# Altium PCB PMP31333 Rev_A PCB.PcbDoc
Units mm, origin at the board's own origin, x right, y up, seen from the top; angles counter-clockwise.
Board outline 35.48 x 25.63 mm, 2 copper layers (Top Layer, Bottom Layer), stack 1.575 mm thick; 18 components, 11 nets, 50 pads, 12 vias.
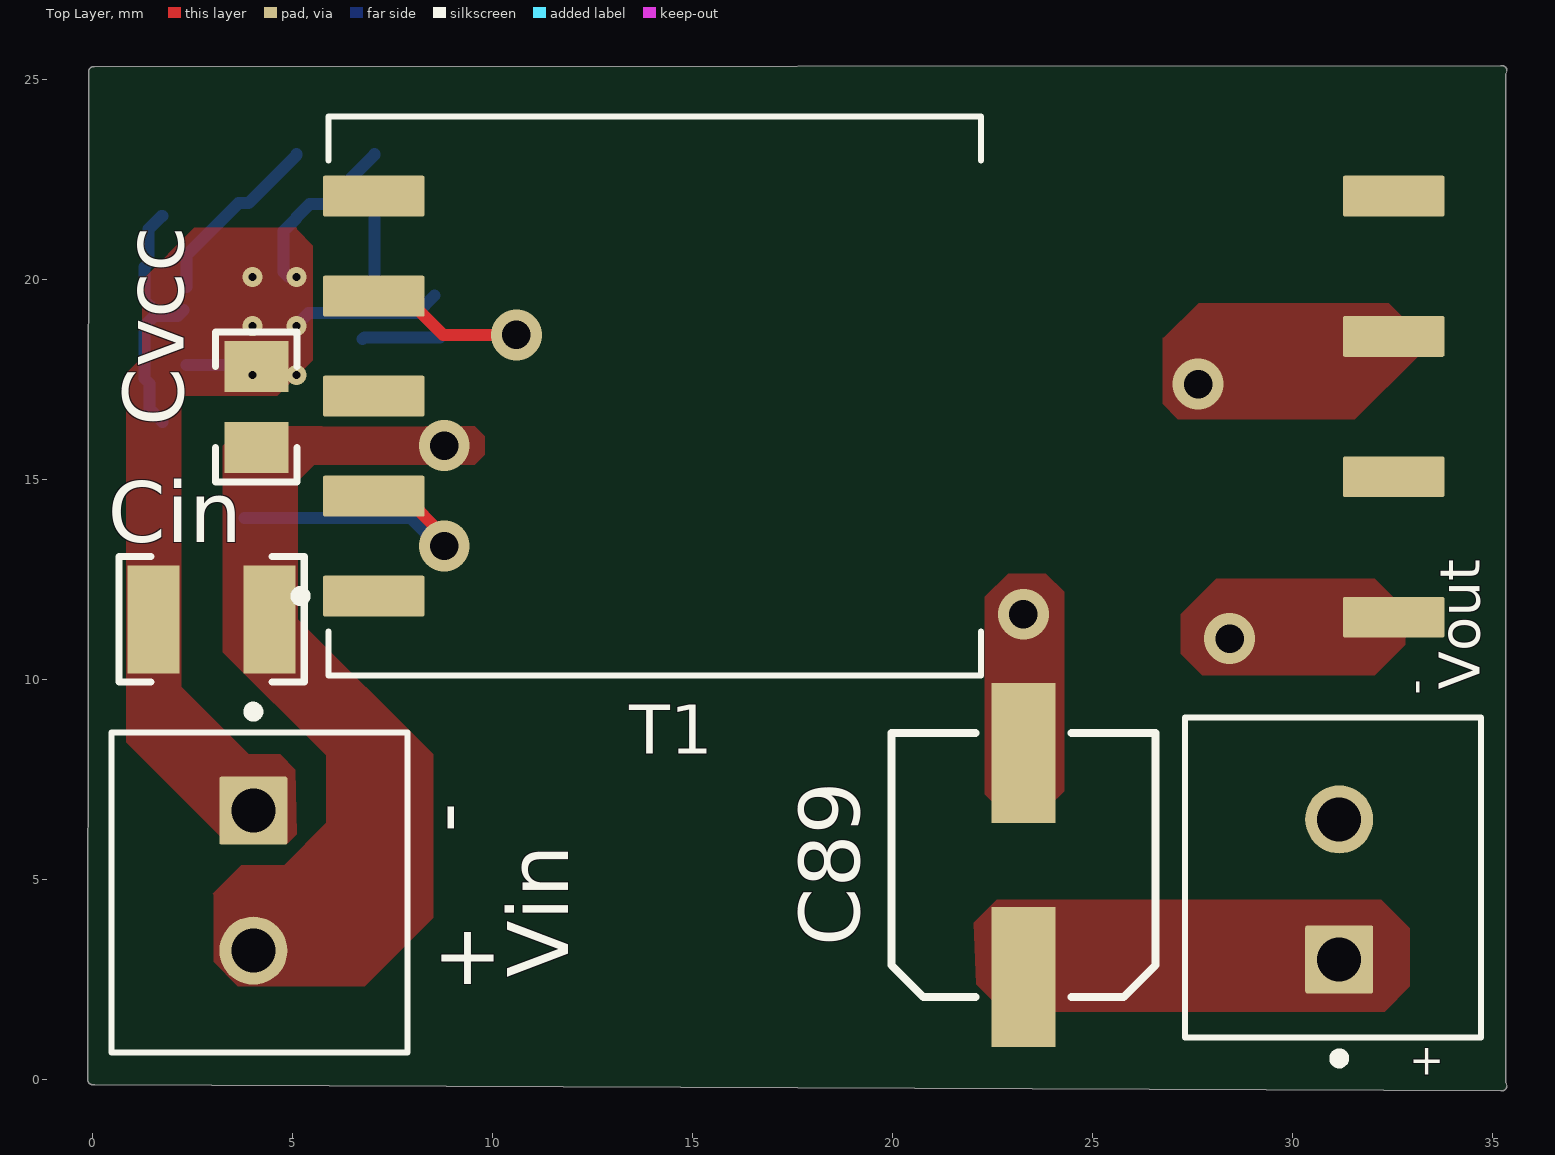
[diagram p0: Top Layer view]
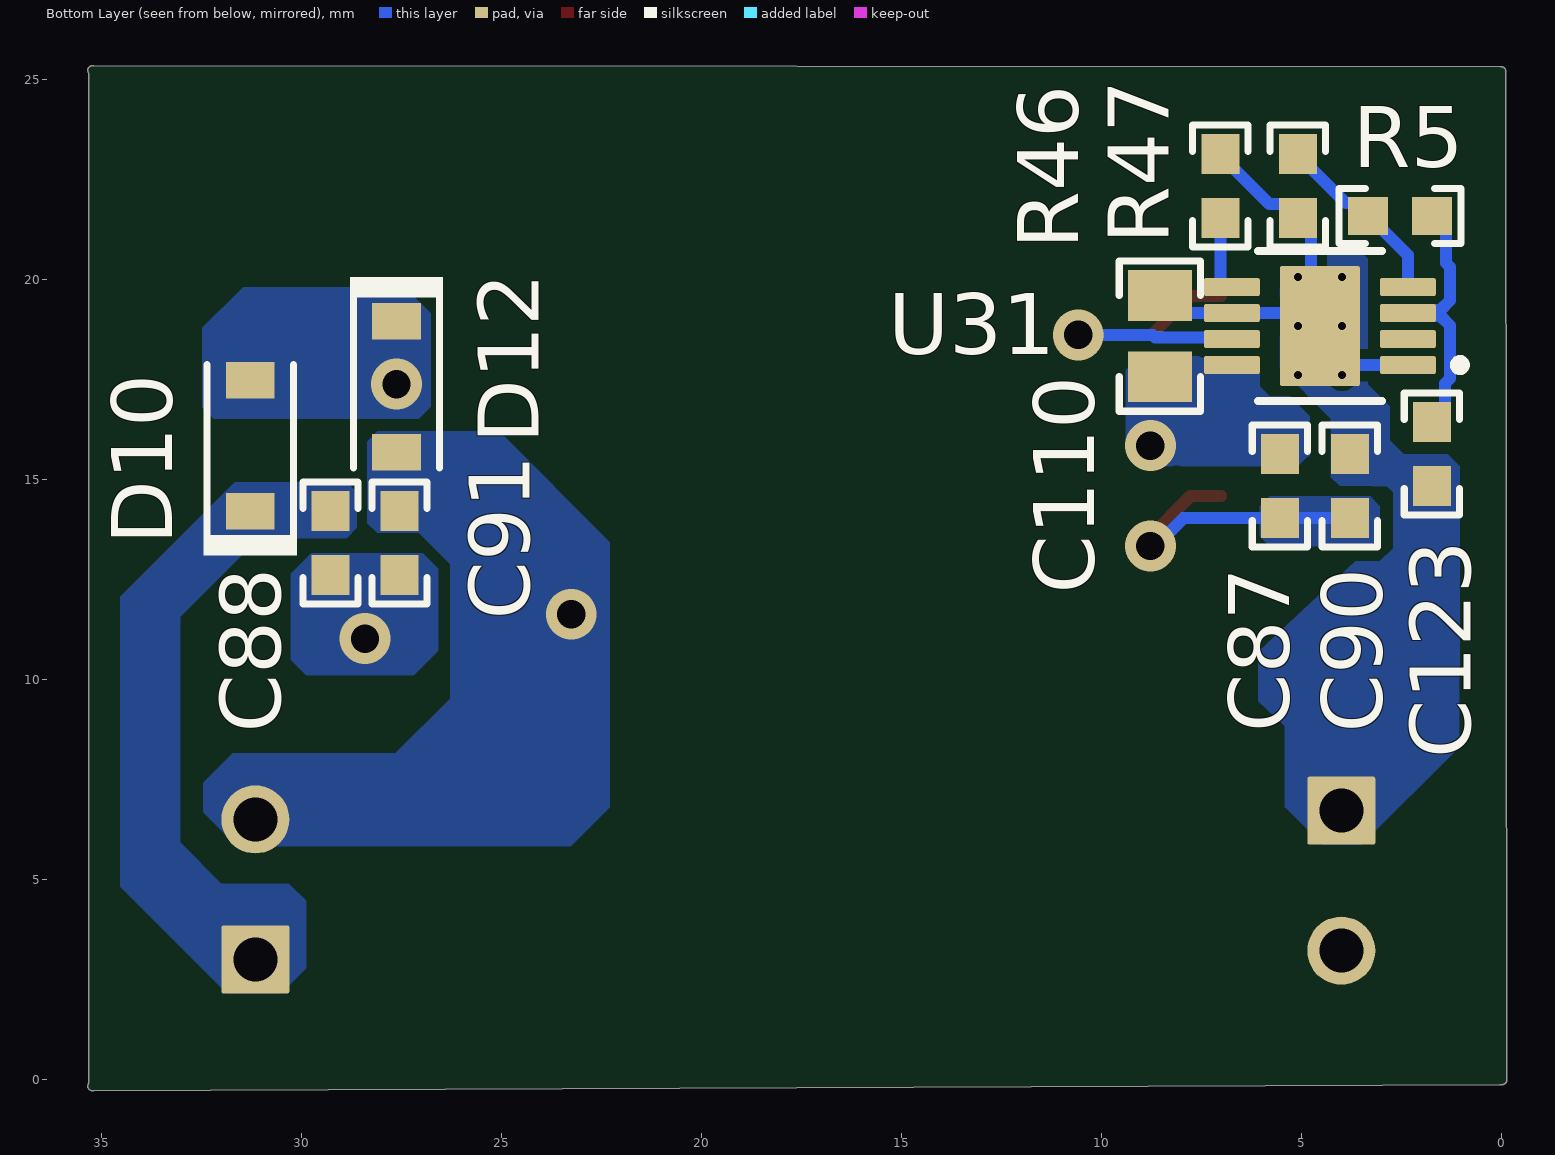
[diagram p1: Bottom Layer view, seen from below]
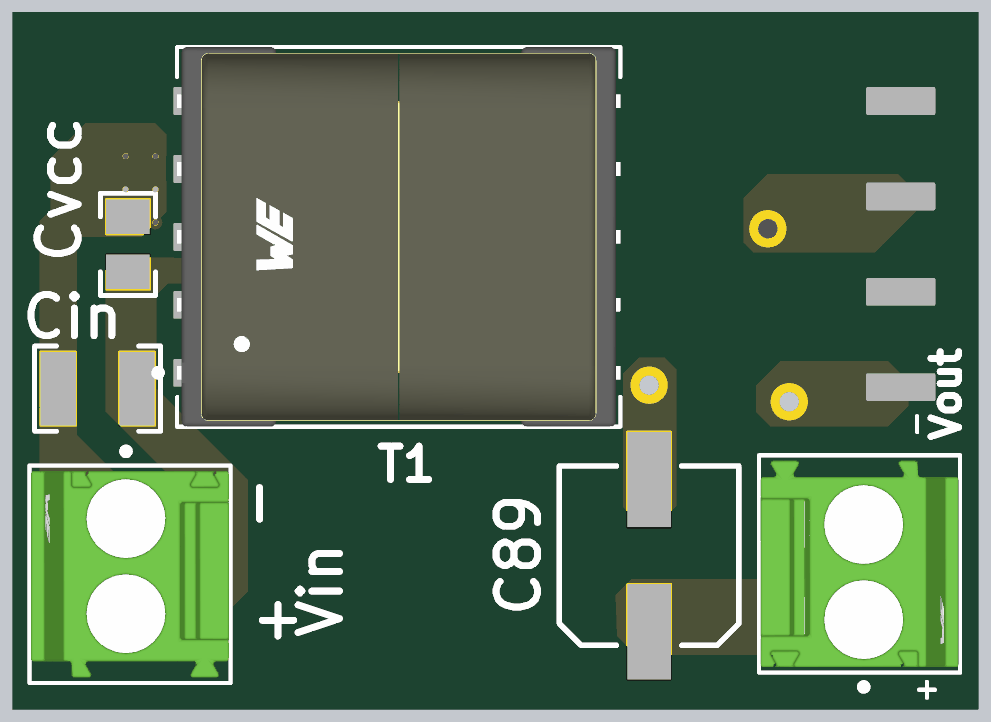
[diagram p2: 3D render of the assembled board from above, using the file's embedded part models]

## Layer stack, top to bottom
Top Solder: solder mask 0.0102, Solder Resist, Dk 3.5
Top Layer: signal copper 0.0356
Dielectric1: dielectric 1.5037, FR-4 High Tg, Dk 4.8
Bottom Layer: signal copper 0.0356
Bottom Solder: solder mask 0.0102, Solder Resist, Dk 3.5

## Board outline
-0.127,0 -0.102,25.197 cw(c0.025,25.197) 0.035,25.324 0.044,25.324 35.202,25.35 35.23,25.35 cw(c35.23,25.222) 35.357,25.222 35.332,25.146 35.332,-0.076 35.357,-0.152 cw(c35.23,-0.152) 35.229,-0.28 35.199,-0.28 0.05,-0.127 0.025,-0.125 cw(c0,0)

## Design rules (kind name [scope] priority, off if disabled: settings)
AcuteAngle [All] p1: minimum=4.50000000000000E+0001 checktracksonly=FALSE
AssemblyTestPointUsage [All] p1: valid=2
BoardOutlineClearance BoardOutlineClearance_MountingHoles [OnCopper and InComponentClass('Mounting Holes')] p1: gap=1 ignorepadtopadclearanceinfootprint=FALSE
BoardOutlineClearance BoardOutlineClearance_Poly [OnCopper and IsPoly] p2: gap=0.635 ignorepadtopadclearanceinfootprint=FALSE
BoardOutlineClearance [OnCopper and Not InComponentClass('Logo') and not InComponentClass('FiducialMark') and not InRegion(1000,500,4000,800) and not InPoly] p3: gap=1.016 ignorepadtopadclearanceinfootprint=FALSE
Clearance Clearance_Keepouts [((IsTrack Or IsArc) And Not InPoly) And IsFree and IsKeepOut vs ((IsTrack Or IsArc) And Not InPoly) And IsFree and IsKeepOut] p1: gap=0 ignorepadtopadclearanceinfootprint=FALSE
Clearance Clearance_Poly [InPolygon] p2: gap=0.254 ignorepadtopadclearanceinfootprint=TRUE
Clearance Clearance_FiducialMark [IsKeepOut and InComponentClass('FiducialMark') vs IsPad and InComponentClass('FiducialMark')] p3: gap=0 ignorepadtopadclearanceinfootprint=FALSE
Clearance [All] p4: gap=0.2 ignorepadtopadclearanceinfootprint=TRUE
ComponentClearance ComponentClearance_MountingHoles_FiducialMarks [InComponentClass('Mounting Holes') vs InComponentClass('FiducialMark')] p1: gap=1.27 collisioncheckmode=3 verticalgap=0.254 showdistances=FALSE
ComponentClearance ComponentClearance_Shunt [InComponentClass('Header') vs InComponentClass('Shunt')] p2: gap=0 collisioncheckmode=3 verticalgap=0 showdistances=FALSE
ComponentClearance ComponentClearance_Logo [InComponentClass('Logo')] p3: gap=0.762 collisioncheckmode=3 verticalgap=0.254 showdistances=FALSE
ComponentClearance ComponentClearance_ScrewToNut [(HasFootprint('NY PMS 440 0025 PH')) vs (HasFootprint('Keystone_1902C'))] p4: gap=0.127 collisioncheckmode=3 verticalgap=0.254 showdistances=FALSE
ComponentClearance ComponentClearance_MountingHoles [InComponentClass('Mounting Holes')] p5: gap=2.54 collisioncheckmode=3 verticalgap=2540 showdistances=FALSE
ComponentClearance ComponentClearance_SmallPassives [HasFootprint('0201*') or HasFootprint('0402*') or HasFootprint('0508') or HasFootprint('0603*') or HasFootprint('0612') or HasFootprint('0805*') or HasFootprint('0815*') or HasFootprint('0830*') or HasFootprint('1206*') or HasFootprint('1210*') or HasFootprint('1808*') or HasFootprint('1812*') or HasFootprint('1825*') or HasFootprint('2010*') or HasFootprint('2220*') or HasFootprint('2225*') or HasFootprint('2512*') or HasFootprint('2728*') or HasFootprint('3518*') vs HasFootprint('0201*') or HasFootprint('0402*') or HasFootprint('0508') or HasFootprint('0603*') or HasFootprint('0612') or HasFootprint('0805*') or HasFootprint('0815*') or HasFootprint('0830*') or HasFootprint('1206*') or HasFootprint('1210*') or HasFootprint('1808*') or HasFootprint('1812*') or HasFootprint('1825*') or HasFootprint('2010*') or HasFootprint('2220*') or HasFootprint('2225*') or HasFootprint('2512*') or HasFootprint('2728*') or HasFootprint('3518*')] p6: gap=0.38 collisioncheckmode=3 verticalgap=0.254 showdistances=FALSE
ComponentClearance ComponentClearance_THtoSMT [IsThruComponent vs IsSMTComponent] p7: gap=0.762 collisioncheckmode=3 verticalgap=0.762 showdistances=FALSE
ComponentClearance ComponentClearance_THtoTH [IsThruComponent vs IsThruComponent] p8: gap=0.508 collisioncheckmode=3 verticalgap=0.762 showdistances=FALSE
ComponentClearance [All] p9: gap=0.508 collisioncheckmode=3 verticalgap=0.254 showdistances=FALSE
DiffPairsRouting [All] p1: maxlimit=2.54 minlimit=0.254 mostfreqgap=0.254 toplayer_minwidth=0.381 toplayer_maxwidth=0.381 toplayer_prefwidth=0.381 bottomlayer_minwidth=0.381 bottomlayer_maxwidth=0.381 bottomlayer_prefwidth=0.381 maxuncoupledlength=25.4
FabricationTestPointUsage TestPointUsage [All] p1: valid=2 allowmultiple=FALSE
FabricationTestpoint Testpoint [All] p1: side=3 testpointundercomponent=TRUE minsize=1.016 maxsize=2.54 preferedsize=1.524 minholesize=0 maxholesize=1.016 preferedholesize=0.813 testpointgrid=0.025 allowsidetop=TRUE allowsidebottom=TRUE usegrid=TRUE gridtolerance=0
FanoutControl Fanout_LCC [IsLCC] p1: bgadir=Out bgaviamode=Centered fanoutstyle=Auto fanoutdirection=Alternating viagrid=0.025 // Fanout_LCC (Default Rule)
FanoutControl Fanout_BGA [IsBGA] p2: bgadir=Out bgaviamode=Centered fanoutstyle=Auto fanoutdirection=Alternating viagrid=0.025 // Fanout_BGA (Default Rule)
FanoutControl Fanout_Default [All] p4: bgadir=Out bgaviamode=Centered fanoutstyle=Auto fanoutdirection=Alternating viagrid=0.025 // Fanout_Default (Default Rule)
FanoutControl Fanout_Small [(CompPinCount < 5)] p5: bgadir=Out bgaviamode=Centered fanoutstyle=Auto fanoutdirection=OutThenIn viagrid=0.025 // Fanout_Small (Default Rule)
HoleSize [All] p1: absolutevalues=TRUE maxlimit=6.375 minlimit=0.2 maxpercent=80.000 minpercent=20.000
MinimumAnnularRing MinimumAnnularRing_ThermalPadVias [IsVia and InAnyComponent] p1: minimumring=0.15
MinimumAnnularRing [All] p2: minimumring=0.2
MinimumSolderMaskSliver MinimumSolderMaskSliver_Logo [InComponentClass('Logo') vs InComponentClass('Logo')] p1: minsoldermaskwidth=0.018
MinimumSolderMaskSliver [All] p2: minsoldermaskwidth=0.1
PlaneConnect [All] p1: planeconnectstyle=Direct reliefexpansion=0.254 reliefentries=4 reliefconductorwidth=0.254 reliefairgap=0.254
PolygonConnect [All] p1: connectstyle=Direct reliefconductorwidth=0.254 reliefentries=4 polygonreliefangle="90 Angle" airgapwidth=0.254
RoutingVias ThermalPadVias [IsVia and InAnyComponent] p1: holewidth=0.2 width=0.5 viastyle="Through Hole" minholewidth=0.2 minwidth=0.5 maxholewidth=0.33 maxwidth=0.6
RoutingVias [All] p2: holewidth=0.406 width=0.864 viastyle="Through Hole" minholewidth=0.2 minwidth=0.61 maxholewidth=1.016 maxwidth=1.651
SilkToSilkClearance SilkToSilkClearance_Pb-FreeLogo [(HasFootprint('Pb-Free_Overlay_Medium') OR HasFootprint('Pb-Free_Overlay_Small')) vs (HasFootprint('Pb-Free_Overlay_Medium') OR HasFootprint('Pb-Free_Overlay_Small'))] p1: silktosilkclearance=0
SilkToSilkClearance [All] p2: silktosilkclearance=0.1
SilkToSolderMaskClearance SilkToComponentPadClearance [(IsPad or IsFill or IsRegion) and InAnycomponent] p1: minsilkscreentomaskgap=0.127 clearancetoexposedcopper=TRUE
SilkToSolderMaskClearance "Silk to Solder Mask Opening" [All] p2: minsilkscreentomaskgap=0.1 clearancetoexposedcopper=FALSE
SolderMaskExpansion [All] p1: expansion=0.05 istentingtop=FALSE
UnRoutedNet [All] p1: checkbadconnections=TRUE
Width [All] p1: maxlimit=0.3 minlimit=0.152 preferedwidth=0.3 minimp=50.000000 maximp=50.000000 favimp=50.000000 checkconnectedcopper=TRUE
15 further rules are at their usual default settings.

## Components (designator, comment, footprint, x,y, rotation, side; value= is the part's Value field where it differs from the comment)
C87 "GRM188R61H225KE11D" 0603 5.551,14.839 r270 bottom value=2.2uF
C88 "GRM188R71E124KA01D" 0603 29.286,13.417 r270 bottom value=0.12uF
C89 "865080445010" WCAP-ASLI_630x770 23.266,5.359 r90 top value=100uF
C90 "GRM188R61H225KE11D" 0603 3.801,14.839 r90 bottom value=2.2uF
C91 "GRM188R71E124KA01D" 0603 27.559,13.417 r90 bottom value=0.12uF
C110 "CGA4J3X7R1H105K125AB" 0805_HV 8.551,18.589 r90 bottom value=1uF
C123 "GCM188R71C105KA64J" 0603 1.751,15.639 r270 bottom value=1uF
Cin "GRM32ER71J106MA12L" 1210_270 2.972,11.506 r180 top value=10uF
Cvcc "CGA4J3X7R1H105K125AB" 0805_HV 4.089,16.815 r90 top value=1uF
D10 "MBR0520LT1G" SOD-123 31.293,15.85 r90 bottom value=20V
D12 "MBR0520LT1G" SOD-123 27.635,17.323 r270 bottom value=20V
R5 "CRCW060316K9FKEA" 0603 2.551,21.589 r180 bottom value=16.9k
R46 "CRCW060315K4FKEA" 0603 7.04,22.339 r270 bottom value=15.4k
R47 "CRCW060315K4FKEA" 0603 5.101,22.339 r90 bottom value=15.4k
T1 "750371825r00" FP-750371825r00_SMT_XFRMR_16MM31_13MM97-MFG 14.051,17.089 r180 top
U31 "UCC25800DGNRQ1" DGN0008G-MFG 4.551,18.839 r0 bottom
Vin "691214110002S" FP-691214110002S_HDR2-MFG 4.166,4.674 r270 top
Vout "691214110002S" FP-691214110002S_HDR2-MFG 31.013,5.055 r90 top

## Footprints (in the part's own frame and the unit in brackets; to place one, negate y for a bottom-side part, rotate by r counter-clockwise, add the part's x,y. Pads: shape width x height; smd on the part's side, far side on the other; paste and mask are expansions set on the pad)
0603 [mm] "0603 from SM-752 data"
  rect 1x0.95 smd: 1(-0.8,0) 2(0.8,0)
  silkscreen extent -1.52,-0.69 1.52,0.69, body extent -0.87,-0.47 0.87,0.47, height 1
0805_HV [mil] "0805 with 30mil clearance between pads"
  rect 50x63 smd: 1(-40,0) 2(40,0)
  silkscreen extent -74,-40 74,40, body extent -43,-29 43,29, height 57
1210_270 [mm] "1210"
  rect 1.3x2.7 smd: 1(-1.45,0) 2(1.45,0)
  silkscreen extent -2.32,-1.57 2.32,1.57, body extent -1.7,-1.35 1.7,1.35, height 2.7
DGN0008G-MFG [mm]
  rrect22% 1.4x0.45 smd paste+0 mask+0: 1(-2.2,0.975) 2(-2.2,0.325) 3(-2.2,-0.325) 4(-2.2,-0.975) 5(2.2,-0.975) 6(2.2,-0.325) 7(2.2,0.325) 8(2.2,0.975)
  rrect5% 2x3 smd paste-1000 mask-1000: 9(0,0)
  silkscreen extent -3.62,-1.88 1.55,1.88, body extent -2.46,-1.5 2.46,1.5, height 1.1
FP-750371825r00_SMT_XFRMR_16MM31_13MM97-MFG [mm]
  rrect10% 2.54x1.02 smd paste+0 mask+0: 1(7.025,5) 2(7.025,2.5) 3(7.025,0) 4(7.025,-2.5) 5(7.025,-5) 6(-18.475,-5) 7(-18.475,-1.49) 8(-18.475,2.02) 9(-18.475,5.53)
  silkscreen extent -8.16,-6.99 8.98,6.99, body extent -8.39,-7.08 8.39,7.08, height 0.25
FP-691214110002S_HDR2-MFG [mm]
  rrect6% 1.7x1.7 hole 1.1 paste-2539.97 mask+0: 1(-2.05,-0.15)
  round 1.7 hole 1.1 paste-2539.97 mask+0: 2(1.45,-0.15)
  silkscreen extent -4.65,-3.7 4,3.7, body extent -4.1,-3.8 4.1,3.8, height 0.25
SOD-123 [mm] "On Semi recommended land pattern"
  rect 0.915x1.22 smd: 1(-1.637,0) 2(1.637,0)
  silkscreen extent -2.74,-1.17 2.03,1.17, body extent -1.93,-0.9 1.93,0.9, height 1.35
WCAP-ASLI_630x770 [mm] "SMD, 2-Leads, Dia 6.3mm"
  rect 3.5x1.6 smd: 1(-2.8,0) 2(2.8,0)
  silkscreen extent -3.3,-3.3 3.3,3.3, body extent -3.3,-3.3 3.3,3.3, height 7.7

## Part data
C87 C90: library part CMP-0007353-5, "CAP, CERM, 2.2 uF, 50 V, +/- 10%, X5R, 0603", Cap_Case=0603, Manufacturer=MuRata, Supplier Part Number 1=490-10733-1-ND, TempCo=X5R, Tolerance_%=10%, Value1=Unknown, Value2=50V, ValueDisplayed=2.2uF
C88 C91: library part CMP-0007408-4, "CAP, CERM, 0.12 uF, 25 V, +/- 10%, X7R, 0603", Cap_Case=0603, Manufacturer=MuRata, Supplier Part Number 1=GRM188R71E124KA01D-ND, TempCo=X7R, Tolerance_%=10%, Value1=Unknown, Value2=25V, ValueDisplayed=0.12uF
C89: library part CMP-0010559-1, "CAP, AL, 100 uF, 25 V, +/- 20%, SMD", Cap_Case=6.3x7.7mm, Manufacturer="Wurth Elektronik", Supplier Part Number 1=732-8438-1-ND, Tolerance_%=20%, Value1=Unknown, Value2=25V, ValueDisplayed=100uF
C110 Cvcc: library part CMP-0007976-2, "CAP, CERM, 1 uF, 50 V, +/- 10%, X7R, AEC-Q200 Grade 1, 0805", Cap_Case=0805, Manufacturer=TDK, Supplier Part Number 1=445-6961-1-ND, TempCo=X7R, Tolerance_%=10%, Value1="0.008782 ohm", Value2=50V, ValueDisplayed=1uF
C123: library part CMP-0079154-1, "CAP, CERM, 1 µF, 16 V,+/- 10%, X7R, AEC-Q200 Grade 1, 0603", Cap_Case=0603, Manufacturer=MuRata, Supplier Part Number 1=490-12657-1-ND, TempCo=X7R, Tolerance_%=10%, Value2=16V, ValueDisplayed=1µF
Cin: library part CMP-0079609-1, "CAP, CERM, 10 µF, 63 V,+/- 20%, X7R, 1210", Cap_Case=1210, Manufacturer=MuRata, Supplier Part Number 1=490-9971-1-ND, TempCo=X7R, Tolerance_%=20%, Value2=63V, ValueDisplayed=10µF
D10 D12: library part CMP-0028524-2, "Diode, Schottky, 20 V, 0.5 A, SOD-123", Manufacturer="ON Semiconductor", Value1=0.5A, Value2=0.385V
R5: library part CMP-0022081-4, "RES, 16.9 k, 1%, 0.1 W, AEC-Q200 Grade 0, 0603", Manufacturer=Vishay-Dale, Power_W=100mW, Supplier Part Number 1=541-16.9KHCT-ND, TempCo="100 ppm/C", Tolerance_%=1%, Value2=0.1W, Value_Code=16k9, ValueDisplayed=16.9k
R46 R47: library part CMP-0022067-4, "RES, 15.4 k, 1%, 0.1 W, AEC-Q200 Grade 0, 0603", Manufacturer=Vishay-Dale, Power_W=100mW, Supplier Part Number 1=541-15.4KHCT-ND, TempCo="100 ppm/C", Tolerance_%=1%, Value2=0.1W, Value_Code=15k4, ValueDisplayed=15.4k
T1: library part CMP-0121486-1, "TRANSFORMER", Frequency_Fixed=500kHz, Manufacturer="Wurth Electronics", Operating Temperature Range="-40°C to +125°C", Voltage_Isolation_Vrms=3kV
U31: library part CMP-0088494-2, "Open Loop LLC Transformer Driver for Isolated Bias Supplies", Manufacturer="Texas Instruments", Max Supply Voltage=36V, Min Supply Voltage=12V, Nominal Supply Current=500uA, Operating Temperature Range="-40°C to +150°C", Switching Frequency=100-2000kHz
Vin Vout: library part CMP-0093089-2, "2 Position Wire to Board Terminal Block Horizontal with Board 0.138\" (3.50mm) Through Hole", Current_A=10A, Digikey Part Number=732-691214110002S-ND, Manufacturer=Wurth, Mouser Part Number=710-691214110002S, Operating Temperature Range="-30°C to +120°C", Voltage_V=300V

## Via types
v1: diameter 1.27, hole 0.711, Top Layer to Bottom Layer, 6 vias
v2: diameter 0.5, hole 0.2, Top Layer to Bottom Layer, 6 vias

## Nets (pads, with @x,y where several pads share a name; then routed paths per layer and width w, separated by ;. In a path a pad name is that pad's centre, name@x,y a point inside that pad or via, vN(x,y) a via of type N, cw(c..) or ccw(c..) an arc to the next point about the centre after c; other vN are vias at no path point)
24V: C87.1 C110.1 Cin.1 Cvcc.1 U31.8 Vin.2
  other v1: 8.788,15.85
GND: C90.2 C110.2 C123.2 Cin.2 Cvcc.2 R46.1 R47.1 U31.1 U31.6 U31.9 Vin.1 | length 10
  Bottom Layer w0.3: U31.1 3.756,17.864 v2(4.001,17.619) ; v2(5.101,18.839) 5.101,18.864 5.401,19.164 U31.6 8.11,19.164 C110.2 ; v2(5.101,20.059) 4.906,20.059 4.776,20.189 4.776,21.214 R47.1 5.101,21.564 5.426,21.889 5.815,21.889 7.04,23.114 R46.1
  other v2: 5.101,17.619 4.001,18.839 4.001,20.059
GND_S: C89.2 C91.2 D12.2 Vout.2
  other v1: 23.266,11.633
NetC87_2: C87.2 C90.1 T1.2 | length 7.7
  Top Layer w0.3: T1.2 7.786,14.589 8.788,13.587 v1(8.788,13.339)
  Bottom Layer w0.3: C90.1 C87.2 7.954,14.039 8.654,13.339 v1(8.788,13.339)
NetC88_1: C88.1 C89.1 D10.1 Vout.1
NetC88_2: C88.2 C91.1 T1.9
  other v1: 28.423,11.024
NetC123_1: C123.1 R5.2 U31.3 | length 7.1
  Bottom Layer w0.3: C123.1 1.426,16.764 1.426,17.398 1.301,17.523 1.301,18.855 1.535,19.089 2.126,19.089 2.276,19.239 1.535,19.239 1.301,19.473 1.301,20.319 1.401,20.419 1.401,21.264 1.726,21.589 R5.2
NetD10_2: D10.2 D12.1 T1.7
  other v1: 27.635,17.389
NetR5_1: R5.1 R47.2 U31.4 | length 4.6
  Bottom Layer w0.3: U31.4 2.351,20.614 3.651,21.914 3.901,21.914 5.101,23.114 R47.2
NetR46_2: R46.2 U31.5 | length 2
  Bottom Layer w0.3: U31.5 6.965,19.814 7.04,19.889 R46.2
NetT1_4: T1.4 U31.7 | length 7.9
  Top Layer w0.3: T1.4 7.786,19.589 8.757,18.618 v1(10.592,18.618)
  Bottom Layer w0.3: U31.7 6.795,18.558 8.677,18.558 8.737,18.618 v1(10.592,18.618)
pads on no net: T1.1 T1.3 T1.5 T1.6 T1.8 U31.2

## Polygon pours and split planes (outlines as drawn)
NetC88_1 on Bottom Layer "Bottom Layer-NetC88_1" (solid, pour order 38): 28.626,13.792 28.88,13.538 31.083,13.538 33.045,11.576 33.045,5.931 32.017,4.902 30.328,4.902 29.896,4.47 29.896,2.781 30.518,2.159 31.877,2.159 34.544,4.826 34.544,12.065 31.674,14.935 28.88,14.935 28.626,14.681
GND on Bottom Layer "Bottom Layer-GND" (solid, pour order 34): 5.424,6.807 5.42,6.807 4.481,5.867 3.511,5.867 1.067,8.311 1.067,10.323 1.051,10.339 1.051,15.339 1.351,15.639 2.457,15.639 2.801,15.983 2.801,16.839 3.351,17.389 3.351,20.521 3.48,20.65 4.362,20.65 4.551,20.839 4.551,21.849 4.801,22.099 5.424,22.099 5.424,22.093 5.551,21.972 5.551,17.804 4.274,16.527 4.274,15.062 4.051,14.839 2.876,14.839 2.718,14.681 2.718,13.284 3.049,12.953 3.665,12.953 6.08,10.711 6.087,10.704 6.087,9.463 5.424,8.838
GND_S on Bottom Layer "Bottom Layer-GND_S" (solid, pour order 30): 32.461,7.417 31.725,8.153 27.661,8.153 26.289,9.525 26.289,12.878 27.076,13.665 28.118,13.665 28.372,13.919 28.372,15.951 28.118,16.205 25.07,16.205 22.301,13.437 22.301,6.807 23.279,5.829 31.61,5.829 32.461,6.68
NetD10_2 on Bottom Layer "NETD10_2_L02_P025" (solid, pour order 25): 27.076,16.527 26.784,16.819 26.784,19.164 27.434,19.814 31.465,19.814 32.487,18.792 32.487,16.815 32.199,16.527
NetC88_2 on Bottom Layer "NETC88_2_L02_P021" (solid, pour order 21): 26.975,13.157 26.594,12.776 26.594,10.719 27.203,10.109 29.896,10.109 30.277,10.49 30.277,12.649 29.769,13.157 29.54,13.157
NetC87_2 on Bottom Layer "NETC87_2_L02_P001" (solid, pour order 1): 6.051,14.339 6.055,13.589 6.051,13.589 5.801,13.339 3.301,13.339 3.051,13.589 3.051,14.339 3.301,14.589 5.801,14.589
24V on Bottom Layer "24V_L02_P000" (solid, pour order 0): 6.051,17.864 6.076,17.864 6.301,18.089 9.038,18.089 9.398,17.729 9.398,15.773 8.964,15.339 5.101,15.339 4.851,15.589 4.801,15.589 4.801,16.589 5.301,17.089 5.801,17.089 6.051,17.339
GND on Top Layer "GND_L01_P036" (solid, pour order 36): 5.068,7.752 4.687,8.133 3.899,8.133 2.21,9.822 2.21,12.957 2.21,17.094 1.24,18.064 0.833,17.658 0.833,8.438 3.38,5.891 4.864,5.891 5.102,6.129
24V on Top Layer "24V_L01_P035" (solid, pour order 35): 4.789,5.364 5.842,6.417 5.842,8.103 3.256,10.688 3.256,15.85 3.739,16.332 9.55,16.332 9.804,16.078 9.804,15.621 9.55,15.367 5.537,15.367 5.131,14.961 5.131,11.506 8.509,8.128 8.509,4.045 6.8,2.337 3.626,2.337 3.023,2.94 3.023,4.623 2.997,4.648 3.713,5.364
NetC88_1 on Top Layer "NETC88_1_L01_P032" (solid, pour order 32): 22.029,3.924 22.606,4.501 32.215,4.501 32.931,3.785 32.931,2.337 32.296,1.702 22.771,1.702 22.085,2.388
GND_S on Top Layer "GND_S_L01_P031" (solid, pour order 31): 22.301,7.137 22.301,12.065 22.885,12.649 23.825,12.649 24.282,12.192 24.282,7.214 23.901,6.833 22.606,6.833 22.555,6.883
NetD10_2 on Top Layer "NETD10_2_L01_P026" (solid, pour order 26): 33.147,18.669 32.404,19.412 27.648,19.412 26.778,18.542 26.746,18.542 26.746,16.891 27.127,16.51 31.557,16.51 33.147,18.1
NetC88_2 on Top Layer "NETC88_2_L01_P022" (solid, pour order 22): 32.817,11.76 32.055,12.522 28.092,12.522 27.203,11.633 27.203,10.643 27.737,10.109 32.055,10.109 32.817,10.871
GND on Top Layer "GND_L01_P019" (solid, pour order 19): 5.507,20.846 5.096,21.257 5.096,21.29 2.542,21.29 1.24,19.988 1.24,18.064 2.21,17.094 4.613,17.094 5.507,17.988

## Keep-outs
Keep-Out Layer:
  text ".Layer_Name" at 14.541,-25.527 h1.52

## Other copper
Top Layer:
  text ".Layer_Name" at 12.542,-25.527 h1.52
Bottom Layer:
  text ".Layer_Name" at 14.541,-25.527 h1.52

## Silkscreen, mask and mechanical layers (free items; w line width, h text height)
Top Overlay:
  text "-" at 33.426,9.627 h0.76 r90
  text "-" at 9.525,6.172 h1.52 r90
  text "+" at 8.499,2.388 h1.52
  text "+" at 32.918,0.127 h0.76
  text ".Layer_Name" at 14.541,-25.527 h1.52
Bottom Overlay:
  text ".Layer_Name" at 14.541,-25.527 h1.52
Top Paste:
  text ".Layer_Name" at 14.541,-25.527 h1.52
Bottom Paste:
  text ".Layer_Name" at 14.541,-25.527 h1.52
Top Solder:
  text ".Layer_Name" at 14.541,-25.527 h1.52
  text ".Layer_Name" at 14.541,-25.527 h1.52
Bottom Solder:
  text ".Layer_Name" at 14.541,-25.527 h1.52
Drill Guide:
  text ".Layer_Name" at 14.541,-25.527 h1.52
M1 Board Outline:
  lines w0.254: -0.025,0 0,25.197 ; 0.019,25.197 35.204,25.222 ; 0.025,0 35.204,-0.152 ; 35.179,-0.152 35.179,25.222
  text ".Layer_Name" at 12.542,-25.527 h1.52
M2 Board Dimensions:
  rectangle: 3.061,-13.881 12.586,-10.706
  rectangle: -0.114,-10.706 3.061,-7.531
  lines w0.178: -0.114,-10.706 25.286,-10.706 ; 3.061,-13.881 3.061,-7.531 ; 6.236,-13.881 6.236,-7.531 ; 12.586,-13.881 12.586,-7.531 ; 18.936,-13.881 18.936,-7.531 ; -0.114,-13.881 -0.114,-7.531 25.286,-7.531 25.286,-13.881 -0.114,-13.881
  text ".Layer_Name" at 12.542,-25.527 h1.52
M3 3D STEP Top:
  text ".Layer_Name" at 12.542,-25.527 h1.52
M4 3D STEP Bottom:
  text ".Layer_Name" at 12.542,-25.527 h1.52
M5 Assembly Top:
  lines w0.254: -8.031,-27.347 140.56,-27.347 ; -8.031,-22.183 140.56,-22.183 ; -8.031,-17.018 -8.031,-32.512 93.696,-32.512 ; 31.999,-32.512 -8.018,-32.512 -8.018,-17.018 140.56,-17.018 140.56,-32.512 81.596,-32.512 ; 49.98,-32.512 49.98,-17.018 ; 76.162,-22.183 76.162,-17.018 ; 94.498,-22.183 94.498,-17.018 ; 107.297,-32.677 107.297,-27.525
  text "PMP31333 Rev_A" at 9.195,1.067 h0.76
  text "COMPONENTS MARKED 'DNP' SHOULD NOT BE POPULATED." at 26.085,-11.811 h1.52
  text "ASSEMBLY VARIANT:" at 26.072,-14.745 h1.52
  text ".VariantName" at 52.186,-14.745 h1.52
  text "PCB VIEWED FROM TOP SIDE" at -6.918,-20.375 h1.52
  text "BOARD #:" at 51.085,-20.375 h1.52
  text ".PRJ_Number" at 62.741,-20.375 h1.52
  text "REV:" at 80.191,-20.375 h1.52
  text ".PCB_Rev" at 86.095,-20.375 h1.52
  text "SVN REV:" at 96.276,-20.375 h1.52
  text ".VersionControl_RevNumber" at 108.829,-20.375 h1.52
  text "TID #:" at 51.085,-25.54 h1.52
  text ".TID" at 62.741,-25.54 h1.52
  text "PLOT NAME =" at -6.918,-30.755 h1.52
  text ".plot_File_Name" at 12.542,-30.755 h1.52
  text "GENERATED    :" at 51.136,-30.755 h1.52
  text ".Print_Date" at 69.521,-30.755 h1.52
  text ".Print_Time" at 84.538,-30.755 h1.52
  text "TEXAS INSTRUMENTS" at 111.656,-30.755 h1.52
M6 Assembly Bottom:
  lines w0.254: -8.044,-22.195 140.56,-22.195 ; -7.993,-27.36 140.56,-27.36 ; 25.619,-32.69 25.619,-27.538 ; 39.418,-22.195 39.418,-17.031 ; 51.82,-32.525 140.56,-32.525 103.517,-32.525 ; 57.92,-32.525 -8.044,-32.525 -8.044,-17.031 140.56,-17.031 ; 58.254,-22.195 58.254,-17.031 ; 84.436,-32.525 84.436,-17.031 ; 140.534,-32.525 140.534,-17.031 ; 140.547,-32.525 140.547,-17.031
  text "COMPONENTS MARKED 'DNP' SHOULD NOT BE POPULATED." at 144.777,-11.798 h1.52
  text ".VariantName" at 110.759,-14.745 h1.52
  text "ASSEMBLY VARIANT:" at 136.15,-14.745 h1.52
  text ".VersionControl_RevNumber" at 26.187,-20.388 h1.52
  text "SVN REV:" at 38.54,-20.388 h1.52
  text ".PCB_Rev" at 48.821,-20.388 h1.52
  text "REV:" at 54.925,-20.388 h1.52
  text ".PRJ_Number" at 70.175,-20.388 h1.52
  text "BOARD #:" at 82.031,-20.388 h1.52
  text "PCB VIEWED FROM BOTTOM SIDE" at 139.434,-20.388 h1.52
  text ".TID" at 70.675,-25.552 h1.52
  text "TID #:" at 82.031,-25.552 h1.52
  text "TEXAS INSTRUMENTS" at 21.36,-30.768 h1.52
  text ".Print_Time" at 51.378,-30.768 h1.52
  text ".Print_Date" at 67.095,-30.768 h1.52
  text "GENERATED    :" at 86.98,-30.768 h1.52
  text ".plot_File_Name" at 122.474,-30.768 h1.52
  text "PLOT NAME =" at 139.434,-30.768 h1.52
M9 Title Sheet:
  drawing of 55 lines, arcs and shapes, not listed
  text "1" at 16.671,131.699 h1.78
  text "2" at 76.564,131.699 h1.78
  text "3" at 136.931,131.699 h1.78
  text "4" at 197.265,131.699 h1.78
  text "A" at -11.201,109.093 h1.78
  text "A" at 224.892,109.093 h1.78
  text "B" at -11.201,61.443 h1.78
  text "B" at 224.892,61.443 h1.78
  text "C" at -11.201,13.792 h1.78
  text "C" at 224.892,13.792 h1.78
  text "PROJECT TITLE:" at 147.803,-14.453 h1.14
  text ".PRJ_Title" at 149.073,-17.839 h1.78
  text "DESIGNED FOR:" at 147.803,-22.098 h1.14
  text ".PRJ_Customer" at 149.073,-25.654 h1.78
  text "FILE NAME:" at 147.803,-29.718 h1.14
  text ".PCB_File_Name_No_Path" at 149.073,-32.766 h1.78
  text "D" at -11.201,-33.757 h1.78
  text "D" at 224.892,-33.757 h1.78
  text "Texas Instruments (TI) and/or its licensors do not warrant the accuracy or completeness of this specification" at 24.371,-36.877 h1.14
  text "ENGINEER:" at 147.803,-37.084 h1.14
  text "LAYOUT BY:" at 186.03,-37.084 h1.14
  text "or any information contained therein. TI and/or its licensors do not warrant that this design will meet" at 23.229,-39.738 h1.14
  text ".PRJ_Engineer" at 149.073,-41.021 h1.78
  text ".PCB_Layout" at 187.312,-41.021 h1.78
  text "the specifications, will be suitable for your application or fit for any particular purpose, or will operate in" at 23.229,-42.6 h1.14
  text "ALTIUM DESIGNER VERSION:" at 186.03,-44.958 h1.14
  text "an implementation. TI and/or its licensors do not warrant that the design is production worthy. You should" at 23.229,-45.462 h1.14
  text "completely validate and test your design implementation to confirm the system functionality for your application." at 24.371,-48.323 h1.02
  text ".print_Scale" at 149.073,-48.345 h1.78
  text ".Application_BuildNumber" at 187.312,-48.345 h1.78
  text "1" at 16.671,-53.721 h1.78
  text "2" at 76.564,-53.721 h1.78
  text "3" at 136.931,-53.721 h1.78
  text "4" at 197.265,-53.721 h1.78
M10 Fab Notes:
  drawing of 189 lines, arcs and shapes, not listed
  text "DESIGN INFORMATION" at 174.117,127.385 h1.52
  text "MIN. TRACK WIDTH:" at 157.746,124.029 h1.52
  text "10" at 185.59,124.03 h1.52
  text "MIL" at 189.521,124.029 h1.52
  text "7.874" at 181.25,121 h1.52
  text "MIN. CLEARANCE:" at 157.746,120.877 h1.52
  text "MIL" at 189.521,120.877 h1.52
  text "MIN. VIA PAD SIZE:" at 157.746,117.724 h1.52
  text "24" at 184.828,117.724 h1.52
  text "MIL" at 189.521,117.724 h1.52
  text "0.05mm (2MIL)" at 175.399,114.424 h1.52
  text "MINIMUM ANNULAR RING" at 149.383,114.216 h1.52
  text "EXTERNAL" at 193.382,114.216 h1.52
  text "PER" at 154.463,111.418 h1.52
  text "IPC-D-275 CLASS 2 LEVEL C" at 160.051,111.418 h1.52
  text "MIL, HOLES" at 197.852,108.866 h1.52
  text "+/-" at 187.884,108.648 h1.52
  text "+/-" at 209.575,108.648 h1.52
  text "REGISTRATION TOLERANCES:" at 149.383,108.621 h1.52
  text "METAL" at 179.857,108.621 h1.52
  text "5" at 194.493,108.621 h1.52
  text "3" at 215.651,108.621 h1.52
  text "MIL" at 218.604,108.621 h1.52
  text "HOLE SIZE TOLERANCE (UNLESS OTHERWISE SPECIFIED):" at 149.383,106.124 h1.52
  text "+/-" at 209.575,106.051 h1.52
  text "3" at 215.651,106.024 h1.52
  text "MIL" at 218.604,106.024 h1.52
  text "MATERIAL:" at 147.484,102.528 h1.52
  text "FR-4 High Tg" at 172.54,99.263 h1.52
  text "X" at 168.871,99.06 h1.52
  text "FR-4" at 158.178,98.945 h1.52
  text "OTHER" at 195.973,98.945 h1.52
  text "62 MIL (1.6mm) +/-10%" at 166.308,95.312 h1.52
  text "X" at 163.258,95.25 h1.52
  text "THICKNESS:" at 149.383,95.104 h1.52
  text "OTHER" at 198.944,95.104 h1.52
  text "TOLERANCE:" at 149.383,91.59 h1.52
  text "X" at 170.928,91.59 h1.52
  text "ANSI IPC-6012 TYPE 3 CLASS 2" at 175.45,91.59 h1.52
  text "OTHER +/-" at 175.449,87.928 h1.52
  text "BOW & TWIST:" at 149.383,84.24 h1.52
  text "X" at 170.928,84.24 h1.52
  text "ANSI IPC-6012 TYPE 3 CLASS 2" at 175.45,84.24 h1.52
  text "OTHER +/-" at 175.449,80.514 h1.52
  text "DRILLING:" at 147.484,77.196 h1.52
  text "NC_DRILL FILES" at 192.213,74.525 h1.52
  text "REFERENCE:" at 149.383,74.425 h1.52
  text "X" at 166.077,74.422 h1.52
  text "AS SHOWN" at 170.598,74.425 h1.52
  text "X" at 188.962,74.425 h1.52
  text "OTHER" at 199.783,70.811 h1.52
  text "PTH COPPER THICKNESS:" at 149.375,70.722 h1.52
  text "X" at 178.312,70.722 h1.52
  text "20-30 um" at 181.563,70.722 h1.52
  text "BOARD FINISH:" at 147.484,66.973 h1.52
  text "SILKSCREEN:" at 151.427,64.176 h1.52
  text "X" at 175.754,64.176 h1.52
  text "TOP" at 178.726,64.176 h1.52
  text "X" at 188.708,64.176 h1.52
  text "BOTTOM" at 191.705,64.176 h1.52
  text "SILKSCREEN COLOR:" at 151.427,60.234 h1.52
  text "X" at 175.729,60.234 h1.52
  text "WHITE" at 178.726,60.234 h1.52
  text "OTHER" at 191.705,60.234 h1.52
  text "X" at 179.056,56.59 h1.52
  text "GREEN" at 182.053,56.59 h1.52
  text "OTHER" at 197.751,56.59 h1.52
  text "SOLDER RESIST COLOR:" at 151.427,56.416 h1.52
  text "X" at 179.056,52.672 h1.52
  text "MATTE" at 182.053,52.672 h1.52
  text "SEMI-GLOSS" at 197.739,52.656 h1.52
  text "IMMERSION GOLD (ENIG)" at 174.433,48.284 h1.52
  text "ENEPIG" at 208.407,48.1 h1.52
  text "SURFACE FINISH:" at 147.484,48.075 h1.52
  text "X" at 169.912,48.075 h1.52
  text "IMM. TIN/SILVER OR EQUIV" at 155.854,44.587 h1.52
  text "OTHER" at 192.213,44.487 h1.52
  text "ARRAY/PANEL:" at 147.484,40.541 h1.52
  text "CUT AND TRIM PER M1 BOARD OUTLINE" at 174.433,40.332 h1.52
  text "N.C. ROUTE" at 174.433,36.878 h1.52
  text "X" at 191.909,36.878 h1.52
  text "V. SCORE" at 196.43,36.878 h1.52
  text "CERTIFICATION:" at 147.484,33.598 h1.52
  text "MATERIALS AND WORKMANSHIP FOR ALL PCBS" at 165.899,33.598 h1.52
  text "TO MEET OR EXCEED THE REQUIREMENTS OF:" at 165.899,31.209 h1.52
  text "X" at 156.692,27.942 h1.52
  text "ANSI IPC-A-600F CLASS ->" at 159.943,27.942 h1.52
  text "X" at 201.802,27.942 h1.52
  text "2" at 204.596,27.942 h1.52
  text "1" at 196.595,27.904 h1.52
  text "3" at 213.588,27.904 h1.52
  text "X" at 177.317,24.191 h1.52
  text "RoHS" at 180.568,24.191 h1.52
  text "OTHER" at 196.935,24.191 h1.52
  text "PER ORDER" at 207.021,24.191 h1.52
  text "ALL BOARDS MUST MEET OR EXCEED UL94-V0 REQUIREMENTS." at 148.184,20.284 h1.52
  text "PCB MUST BEAR THE UL94V-0 UL REGISTERED MATERIAL ID NUMBER" at 148.184,17.336 h1.52
  text "ADDITIONAL REQUIREMENTS:" at 147.484,13.032 h1.52
  text "MICROSECTION:" at 149.383,10.311 h1.52
  text "YES" at 172.389,10.311 h1.52
  text "REQUIRED" at 194.271,6.645 h1.52
  text "BARE BOARD ELEC. TEST:" at 149.383,6.573 h1.52
  text "NONE" at 182.549,6.573 h1.52
  text "X" at 191.274,6.573 h1.52
  text "PER ORDER" at 209.308,6.573 h1.52
  text "XX MIL VIAS REQUIRE NON-CONDUCTIVE FILL AND PLANARIZE" at 153.654,1.367 h1.5
  text "XX MIL VIAS REQUIRE CONDUCTIVE FILL AND PLANARIZE" at 153.857,-1.274 h1.52
  text "OUTER XX MIL TRACES REQUIRE 50 OHM SINGLE-ENDED IMPEDANCE" at 153.832,-5.424 h1.47
  text "LAYER 2 & 3 (INNER LAYERS) XX MIL WIDE, XX MIL SPACE / TRACES REQUIRE 100 OHM DIFFERENTIAL IMPEDANCE" at 153.629,-11.411 h1.52
  text ".Layer_Name" at 12.542,-25.527 h1.52
M11 Gerber Information:
  lines w0.254: -8.031,-27.347 140.56,-27.347 ; -8.031,-22.183 140.56,-22.183 ; -8.031,-17.018 -8.031,-32.512 93.696,-32.512 ; 31.999,-32.512 -8.018,-32.512 -8.018,-17.018 140.56,-17.018 140.56,-32.512 81.596,-32.512 ; 49.98,-32.512 49.98,-17.018 ; 76.162,-22.183 76.162,-17.018 ; 94.498,-22.183 94.498,-17.018 ; 107.297,-32.677 107.297,-27.525
  text "ALL ARTWORK VIEWED FROM TOP SIDE" at -6.918,-20.375 h1.52
  text "BOARD #:" at 51.085,-20.375 h1.52
  text ".PRJ_Number" at 62.741,-20.375 h1.52
  text "REV:" at 80.191,-20.375 h1.52
  text ".PCB_Rev" at 86.095,-20.375 h1.52
  text "SVN REV:" at 96.276,-20.375 h1.52
  text ".VersionControl_RevNumber" at 108.829,-20.375 h1.52
  text "LAYER NAME =" at -6.918,-25.527 h1.52
  text "TID #:" at 51.085,-25.54 h1.52
  text ".TID" at 62.741,-25.54 h1.52
  text "PLOT NAME =" at -6.918,-30.755 h1.52
  text ".plot_File_Name" at 12.542,-30.755 h1.52
  text "GENERATED    :" at 51.136,-30.755 h1.52
  text ".Print_Date" at 69.521,-30.755 h1.52
  text ".Print_Time" at 84.538,-30.755 h1.52
  text "TEXAS INSTRUMENTS" at 111.656,-30.755 h1.52
M12 Stackup:
  drawing of 191 lines, arcs and shapes, not listed
  text "Layer" at 27.775,123.012 h1.52
  text "Name" at 38.187,123.012 h1.52
  text "Material" at 61.802,123.012 h1.52
  text "Thickness" at 83.64,123.012 h1.52
  text "Constant" at 100.146,123.012 h1.52
  text "Board Layer Stack" at 114.621,123.012 h1.52
  text "Top Overlay" at 38.187,119.964 h1.52
  text "Top Solder" at 38.187,116.916 h1.52
  text "Solder Resist" at 61.802,116.916 h1.52
  text "0,40mil" at 83.64,116.916 h1.52
  text "3.5" at 100.146,116.916 h1.52
  text "1" at 27.775,113.868 h1.52
  text "Top Layer" at 38.187,113.868 h1.52
  text "1,40mil" at 83.64,113.868 h1.52
  text "Dielectric1" at 38.187,110.82 h1.52
  text "FR-4 High Tg" at 61.802,110.82 h1.52
  text "59,20mil" at 83.64,110.82 h1.52
  text "4.8" at 100.146,110.82 h1.52
  text "2" at 27.775,107.772 h1.52
  text "Bottom Layer" at 38.187,107.772 h1.52
  text "1,40mil" at 83.64,107.772 h1.52
  text "Bottom Solder" at 38.187,104.724 h1.52
  text "Solder Resist" at 61.802,104.724 h1.52
  text "0,40mil" at 83.64,104.724 h1.52
  text "3.5" at 100.146,104.724 h1.52
  text "Bottom Overlay" at 38.187,101.676 h1.52
  text ".Layer_Name" at 12.542,-25.527 h1.52
M13 Component Bodies Top:
  text ".Layer_Name" at 12.542,-25.527 h1.52
M14 Component Bodies Bottom:
  text ".Layer_Name" at 12.542,-25.527 h1.52
M15 Courtyards Top:
  text ".Layer_Name" at 12.542,-25.527 h1.52
M16 Courtyards Bottom:
  text ".Layer_Name" at 12.542,-25.527 h1.52
Drill Drawing:
  circle w0.254: c64.306,90.837 r0.702
  lines w0.254: 63.604,84.17 63.955,84.17 64.306,83.819 64.657,84.17 65.008,84.17 64.657,84.521 65.008,84.872 64.657,84.872 64.306,85.223 63.955,84.872 63.604,84.872 63.955,84.521 63.604,84.17 ; 63.604,88.381 65.008,88.381 64.306,86.977 63.604,88.381
  lines w0.305: 62.332,82.872 144.41,82.872 ; 62.332,92.346 144.41,92.346 ; 70.914,79.713 70.914,95.504 ; 79.347,79.713 79.347,95.504 ; 95.516,79.713 95.516,95.504 ; 102.098,79.713 102.098,95.504 ; 111.627,79.713 111.627,95.504 ; 130.023,79.713 130.023,95.504 ; 62.332,79.713 144.41,79.713 144.41,95.504 62.332,95.504 62.332,79.713
  text "Symbol" at 64.226,93.293 h1.83
  text "Quantity" at 71.861,93.293 h1.83
  text "Finished Hole Size" at 80.294,93.293 h1.83
  text "Plated" at 96.463,93.293 h1.83
  text "Hole Type" at 103.045,93.293 h1.83
  text "Drill Layer Pair" at 112.575,93.293 h1.83
  text "Hole Tolerance" at 130.97,93.293 h1.83
  text "6" at 71.861,90.135 h1.52
  text "7.87mil (0.200mm)" at 80.294,90.135 h1.52
  text "PTH" at 96.463,90.135 h1.52
  text "Round" at 103.045,90.135 h1.52
  text "Top Layer - Bottom Layer" at 112.575,90.135 h1.52
  text "6" at 71.861,86.977 h1.52
  text "28.00mil (0.711mm)" at 80.294,86.977 h1.52
  text "PTH" at 96.463,86.977 h1.52
  text "Round" at 103.045,86.977 h1.52
  text "Top Layer - Bottom Layer" at 112.575,86.977 h1.52
  text "4" at 71.861,83.819 h1.52
  text "43.31mil (1.100mm)" at 80.294,83.819 h1.52
  text "PTH" at 96.463,83.819 h1.52
  text "Round" at 103.045,83.819 h1.52
  text "Top Layer - Bottom Layer" at 112.575,83.819 h1.52
  text "16 Total" at 71.861,80.661 h1.52
  text ".Layer_Name" at 12.542,-25.527 h1.52
M17 Embedded Cavity:
  text ".Layer_Name" at 12.542,-25.527 h1.52
M18 Embedded Assembly:
  text ".Layer_Name" at 12.542,-25.527 h1.52
M19 Embedded Keepout:
  text ".Layer_Name" at 12.642,-25.627 h1.52

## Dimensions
0,0 to 0.019,25.197 on M2 Board Dimensions
0,0 to 35.179,-0.152 on M2 Board Dimensions
-0.114,-13.881 to 25.286,-13.881 on M2 Board Dimensions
